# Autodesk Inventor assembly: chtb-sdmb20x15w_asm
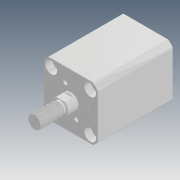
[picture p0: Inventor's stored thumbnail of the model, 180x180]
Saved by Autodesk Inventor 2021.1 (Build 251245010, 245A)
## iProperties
Company: Microsoft
Created: 2018-05
Part Number: chtb-sdmb20x15w_asm
Description: STEP AP214
Document SubType Name: Assembly
Designer: user
Title: chtb-sdmb20x15w_asm.STEP
Author: Windows
Revision Number: ÈÎºÎ
Sending System: SolidWorks 2015
Preprocessor: SwSTEP 2.0
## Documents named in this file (4)
- D:\Vault_2016\Projekty\Clamptek\Hydraulic\CHTB\CHTB-20\Inventor\CHTB-SDMB20x15W\chtb-sdmb20x15w_asm.iam
- D:\Vault_2016\Projekty\Clamptek\Hydraulic\CHTB\CHTB-20\Inventor\CHTB-SDMB20x15W\CHTB-SDMB20X15NBT.ipt
- D:\Vault_2016\Projekty\Clamptek\Hydraulic\CHTB\CHTB-20\Inventor\CHTB-SDMB20x15W\CHTB-SDMB20X15WHSG.ipt
- D:\Vault_2016\Projekty\Clamptek\Hydraulic\CHTB\CHTB-20\Inventor\CHTB-SDMB20x15W\QG_3.ipt
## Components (3 placed, 3 different names)
1. CHTB-SDMB20X15NBT_1
2. CHTB-SDMB20X15WHSG_2
3. QG_3_3
